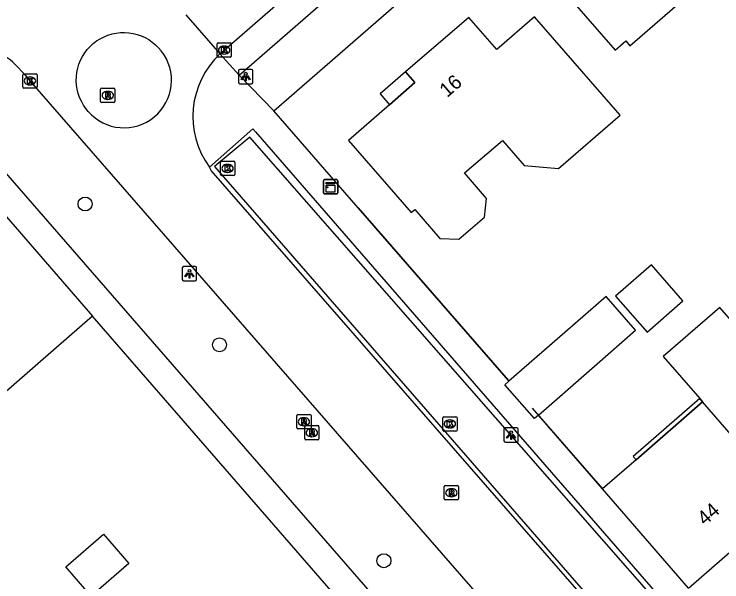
# Model space of a CAD drawing. Extents: x 155888 to 156864, y 383882 to 384671.
# Drawn here: x 156371.55 to 156421.04, y 384408.33 to 384448.02 of the extents above; entities that cross this region are included whole.
import ezdxf

# ---------------------------------------------------------------- set-up
doc = ezdxf.new("R2010")
doc.units = 0
for name, color, linetype in [('IMGEO_Boom', 7, 'Continuous'), ('IMGEO_Greppel_droge_sloot', 7, 'Continuous'), ('IMGEO_Kast', 7, 'Continuous'), ('IMGEO_Kolk', 7, 'Continuous'), ('IMGEO_Lichtpunt', 7, 'Continuous'), ('IMGEO_Muur', 7, 'Continuous'), ('IMGEO_Pand', 7, 'Continuous'), ('IMGEO_Pand_nummerreeks', 7, 'Continuous'), ('IMGEO_Pand_overbouw', 7, 'Continuous'), ('IMGEO_Rijbaan_lokaal_gesloten', 7, 'Continuous'), ('IMGEO_Rijbaan_lokaal_open', 7, 'Continuous'), ('IMGEO_Rioolput', 7, 'Continuous'), ('IMGEO_Voetpad_open', 7, 'Continuous')]:
    doc.layers.add(name, color=color, linetype=linetype)

msp = doc.modelspace()

# ---------------------------------------------------------------- linework, layer by layer
at = {"layer": 'IMGEO_Boom'}
for centre in [(156376.512, 384434.748), (156385.91, 384424.901), (156397.411, 384409.805)]:
    msp.add_circle(centre, 0.489, dxfattribs=at)
at = {"layer": 'IMGEO_Greppel_droge_sloot'}
msp.add_lwpolyline([(156417.878, 384400.227), (156418.055, 384400.375), (156420.409, 384402.472), (156388.034, 384439.426), (156385.569, 384437.381), (156417.878, 384400.227)], dxfattribs=at)
at = {"layer": 'IMGEO_Kast'}
for p, q in [((156393.178, 384435.529), (156393.178, 384436.37)), ((156393.178, 384436.37), (156393.178, 384435.529)), ((156393.253, 384436.454), (156394.094, 384436.454)), ((156394.094, 384436.454), (156393.253, 384436.454)), ((156394.178, 384436.379), (156394.178, 384435.538)), ((156394.178, 384435.538), (156394.178, 384436.379)), ((156394.103, 384435.454), (156393.262, 384435.454)), ((156393.262, 384435.454), (156394.103, 384435.454))]:
    msp.add_line(p, q, dxfattribs=at)
for points in [[(156393.373, 384436.244), (156393.973, 384436.244), (156393.973, 384436.159), (156393.373, 384436.159), (156393.373, 384436.244)], [(156393.373, 384436.069), (156393.973, 384436.069), (156393.973, 384435.58), (156393.373, 384435.58), (156393.373, 384436.069)]]:
    msp.add_lwpolyline(points, dxfattribs=at)
msp.add_circle((156393.457, 384435.918), 0.0377, dxfattribs=at)
for centre, start, end in [((156393.256, 384436.376), 92.4484, 184.2845), ((156393.256, 384436.376), 92.4484, 184.2845), ((156394.1, 384436.376), 2.4484, 94.2845), ((156394.1, 384436.376), 2.4484, 94.2845), ((156393.256, 384435.532), 182.4484, 274.2845), ((156393.256, 384435.532), 182.4484, 274.2845), ((156394.1, 384435.532), 272.4484, 4.2845), ((156394.1, 384435.532), 272.4484, 4.2845)]:
    msp.add_arc(centre, 0.0779, start, end, dxfattribs=at)
at = {"layer": 'IMGEO_Kolk'}
for p, q in [((156385.738, 384445.086), (156385.738, 384445.938)), ((156385.813, 384446.012), (156386.665, 384446.012)), ((156386.226, 384445.792), (156386.251, 384445.792)), ((156386.739, 384445.938), (156386.739, 384445.086)), ((156386.249, 384445.232), (156386.224, 384445.232)), ((156386.665, 384445.012), (156385.813, 384445.012)), ((156372.157, 384442.931), (156372.157, 384443.783)), ((156372.232, 384443.857), (156373.084, 384443.857)), ((156372.645, 384443.637), (156372.67, 384443.637)), ((156373.158, 384443.783), (156373.158, 384442.931)), ((156372.668, 384443.077), (156372.643, 384443.077)), ((156373.084, 384442.857), (156372.232, 384442.857)), ((156385.976, 384436.809), (156385.976, 384437.661)), ((156386.051, 384437.735), (156386.903, 384437.735)), ((156386.977, 384437.661), (156386.977, 384436.809)), ((156386.464, 384437.515), (156386.489, 384437.515)), ((156386.903, 384436.735), (156386.051, 384436.735)), ((156386.487, 384436.955), (156386.462, 384436.955)), ((156401.598, 384419.87), (156402.45, 384419.87)), ((156401.523, 384418.944), (156401.523, 384419.796)), ((156402.011, 384419.65), (156402.036, 384419.65)), ((156402.524, 384419.796), (156402.524, 384418.944)), ((156402.45, 384418.87), (156401.598, 384418.87)), ((156402.034, 384419.09), (156402.009, 384419.09))]:
    msp.add_line(p, q, dxfattribs=at)
for points in [[(156385.738, 384445.086), (156385.738, 384445.938)], [(156385.813, 384446.012), (156386.665, 384446.012)], [(156386.059, 384445.712), (156386.182, 384445.712), (156386.182, 384445.561), (156386.312, 384445.712), (156386.476, 384445.712), (156386.33, 384445.561), (156386.483, 384445.312), (156386.331, 384445.312), (156386.246, 384445.476), (156386.182, 384445.409), (156386.182, 384445.312), (156386.059, 384445.312), (156386.059, 384445.712)], [(156386.739, 384445.938), (156386.739, 384445.086)], [(156386.665, 384445.012), (156385.813, 384445.012)], [(156372.157, 384442.931), (156372.157, 384443.783)], [(156372.232, 384443.857), (156373.084, 384443.857)], [(156373.158, 384443.783), (156373.158, 384442.931)], [(156372.478, 384443.557), (156372.601, 384443.557), (156372.601, 384443.406), (156372.731, 384443.557), (156372.895, 384443.557), (156372.749, 384443.406), (156372.902, 384443.157), (156372.75, 384443.157), (156372.665, 384443.321), (156372.601, 384443.254), (156372.601, 384443.157), (156372.478, 384443.157), (156372.478, 384443.557)], [(156373.084, 384442.857), (156372.232, 384442.857)], [(156385.976, 384436.809), (156385.976, 384437.661)], [(156386.051, 384437.735), (156386.903, 384437.735)], [(156386.977, 384437.661), (156386.977, 384436.809)], [(156386.297, 384437.435), (156386.42, 384437.435), (156386.42, 384437.284), (156386.55, 384437.435), (156386.714, 384437.435), (156386.568, 384437.284), (156386.721, 384437.035), (156386.569, 384437.035), (156386.484, 384437.199), (156386.42, 384437.132), (156386.42, 384437.035), (156386.297, 384437.035), (156386.297, 384437.435)], [(156386.903, 384436.735), (156386.051, 384436.735)], [(156401.598, 384419.87), (156402.45, 384419.87)], [(156401.523, 384418.944), (156401.523, 384419.796)], [(156401.844, 384419.57), (156401.967, 384419.57), (156401.967, 384419.419), (156402.097, 384419.57), (156402.261, 384419.57), (156402.115, 384419.419), (156402.268, 384419.17), (156402.116, 384419.17), (156402.031, 384419.334), (156401.967, 384419.267), (156401.967, 384419.17), (156401.844, 384419.17), (156401.844, 384419.57)], [(156402.524, 384419.796), (156402.524, 384418.944)], [(156402.45, 384418.87), (156401.598, 384418.87)]]:
    msp.add_lwpolyline(points, dxfattribs=at)
for centre, start, end in [((156385.815, 384445.936), 91.552, 178.448), ((156385.815, 384445.936), 91.552, 178.448), ((156386.663, 384445.936), 1.552, 88.448), ((156386.663, 384445.936), 1.552, 88.448), ((156385.815, 384445.088), 181.552, 268.448), ((156385.815, 384445.088), 181.552, 268.448), ((156386.663, 384445.088), 271.552, 358.448), ((156386.663, 384445.088), 271.552, 358.448), ((156372.234, 384443.781), 91.552, 178.448), ((156372.234, 384443.781), 91.552, 178.448), ((156373.082, 384443.781), 1.552, 88.448), ((156373.082, 384443.781), 1.552, 88.448), ((156372.234, 384442.933), 181.552, 268.448), ((156372.234, 384442.933), 181.552, 268.448), ((156373.082, 384442.933), 271.552, 358.448), ((156373.082, 384442.933), 271.552, 358.448), ((156386.053, 384437.659), 91.552, 178.448), ((156386.053, 384437.659), 91.552, 178.448), ((156386.901, 384437.659), 1.552, 88.448), ((156386.901, 384437.659), 1.552, 88.448), ((156386.053, 384436.811), 181.552, 268.448), ((156386.053, 384436.811), 181.552, 268.448), ((156386.901, 384436.811), 271.552, 358.448), ((156386.901, 384436.811), 271.552, 358.448), ((156401.6, 384419.794), 91.552, 178.448), ((156401.6, 384419.794), 91.552, 178.448), ((156402.448, 384419.794), 1.552, 88.448), ((156402.448, 384419.794), 1.552, 88.448), ((156401.6, 384418.946), 181.552, 268.448), ((156401.6, 384418.946), 181.552, 268.448), ((156402.448, 384418.946), 271.552, 358.448), ((156402.448, 384418.946), 271.552, 358.448)]:
    msp.add_arc(centre, 0.0765, start, end, dxfattribs=at)
for centre, major_axis, ratio, start_param, end_param in [((156386.225, 384445.512), (-0.387, 0.002), 0.722429, 4.712389, 7.853982), ((156386.25, 384445.512), (-0.39, 0.002), 0.717154, 1.570796, 4.712389), ((156372.644, 384443.357), (-0.387, 0.002), 0.722429, 4.712389, 7.853982), ((156372.669, 384443.357), (-0.39, 0.002), 0.717154, 1.570796, 4.712389), ((156386.463, 384437.235), (-0.387, 0.002), 0.722429, 4.712389, 7.853982), ((156386.488, 384437.235), (-0.39, 0.002), 0.717154, 1.570796, 4.712389), ((156402.01, 384419.37), (-0.387, 0.002), 0.722429, 4.712389, 7.853982), ((156402.035, 384419.37), (-0.39, 0.002), 0.717154, 1.570796, 4.712389)]:
    msp.add_ellipse(centre, major_axis=major_axis, ratio=ratio, start_param=start_param, end_param=end_param, dxfattribs=at)
at = {"layer": 'IMGEO_Lichtpunt'}
for p, q in [((156387.248, 384444.063), (156387.248, 384443.256)), ((156387.248, 384444.063), (156387.248, 384443.256)), ((156388.15, 384444.158), (156387.342, 384444.158)), ((156388.15, 384444.158), (156387.342, 384444.158)), ((156388.244, 384443.256), (156388.244, 384444.063)), ((156388.244, 384443.256), (156388.244, 384444.063)), ((156387.342, 384443.162), (156388.15, 384443.162)), ((156387.342, 384443.162), (156388.15, 384443.162)), ((156383.311, 384430.277), (156383.311, 384429.47)), ((156383.311, 384430.277), (156383.311, 384429.47)), ((156384.213, 384430.372), (156383.405, 384430.372)), ((156384.213, 384430.372), (156383.405, 384430.372)), ((156384.307, 384429.47), (156384.307, 384430.277)), ((156384.307, 384429.47), (156384.307, 384430.277)), ((156383.405, 384429.376), (156384.213, 384429.376)), ((156383.405, 384429.376), (156384.213, 384429.376)), ((156405.808, 384418.991), (156405.808, 384418.184)), ((156405.808, 384418.991), (156405.808, 384418.184)), ((156406.71, 384419.086), (156405.902, 384419.086)), ((156406.71, 384419.086), (156405.902, 384419.086)), ((156406.804, 384418.184), (156406.804, 384418.991)), ((156406.804, 384418.184), (156406.804, 384418.991)), ((156405.902, 384418.09), (156406.71, 384418.09)), ((156405.902, 384418.09), (156406.71, 384418.09))]:
    msp.add_line(p, q, dxfattribs=at)
for points in [[(156387.622, 384443.727), (156387.661, 384443.699), (156387.473, 384443.437), (156387.435, 384443.464), (156387.622, 384443.727)], [(156387.724, 384443.679), (156387.771, 384443.679), (156387.771, 384443.357), (156387.724, 384443.357), (156387.724, 384443.679)], [(156387.834, 384443.699), (156387.872, 384443.726), (156388.059, 384443.464), (156388.02, 384443.436), (156387.834, 384443.699)], [(156383.685, 384429.941), (156383.724, 384429.913), (156383.536, 384429.651), (156383.498, 384429.678), (156383.685, 384429.941)], [(156383.787, 384429.893), (156383.834, 384429.893), (156383.834, 384429.571), (156383.787, 384429.571), (156383.787, 384429.893)], [(156383.897, 384429.913), (156383.935, 384429.94), (156384.122, 384429.678), (156384.083, 384429.65), (156383.897, 384429.913)], [(156406.182, 384418.655), (156406.221, 384418.627), (156406.033, 384418.365), (156405.995, 384418.392), (156406.182, 384418.655)], [(156406.284, 384418.607), (156406.331, 384418.607), (156406.331, 384418.285), (156406.284, 384418.285), (156406.284, 384418.607)], [(156406.394, 384418.627), (156406.432, 384418.654), (156406.619, 384418.392), (156406.58, 384418.364), (156406.394, 384418.627)]]:
    msp.add_lwpolyline(points, dxfattribs=at)
for centre in [(156387.747, 384443.861), (156383.81, 384430.075), (156406.307, 384418.789)]:
    msp.add_circle(centre, 0.0994, dxfattribs=at)
for centre, start, end in [((156387.342, 384444.063), 90, 180), ((156387.342, 384444.063), 90, 180), ((156388.15, 384444.063), 0, 90), ((156388.15, 384444.063), 0, 90), ((156387.342, 384443.256), 180, 270), ((156387.342, 384443.256), 180, 270), ((156388.15, 384443.256), 270, 0), ((156388.15, 384443.256), 270, 360), ((156383.405, 384430.277), 90, 180), ((156383.405, 384430.277), 90, 180), ((156384.213, 384430.277), 0, 90), ((156384.213, 384430.277), 0, 90), ((156383.405, 384429.47), 180, 270), ((156383.405, 384429.47), 180, 270), ((156384.213, 384429.47), 270, 0), ((156384.213, 384429.47), 270, 360), ((156405.902, 384418.991), 90, 180), ((156405.902, 384418.991), 90, 180), ((156406.71, 384418.991), 0, 90), ((156406.71, 384418.991), 0, 90), ((156405.902, 384418.184), 180, 270), ((156405.902, 384418.184), 180, 270), ((156406.71, 384418.184), 270, 0), ((156406.71, 384418.184), 270, 360)]:
    msp.add_arc(centre, 0.0946, start, end, dxfattribs=at)
at = {"layer": 'IMGEO_Muur'}
for points in [[(156395.616, 384434.473), (156406.119, 384422.397)], [(156404.4, 384395.417), (156377.02, 384426.898)], [(156407.789, 384420.472), (156412.691, 384414.822)]]:
    msp.add_lwpolyline(points, dxfattribs=at)
at = {"layer": 'IMGEO_Pand'}
for points in [[(156413.577, 384445.494), (156414.331, 384446.149), (156414.62, 384445.817), (156420.398, 384450.838), (156422.875, 384447.986), (156425.485, 384450.254), (156426.684, 384448.874), (156429.083, 384450.958), (156421.59, 384459.589), (156418.053, 384456.578), (156416.369, 384458.556), (156415.608, 384457.909), (156415.33, 384458.236), (156413.8, 384456.905), (156413.367, 384457.402), (156409.892, 384454.38), (156410.325, 384453.882), (156408.78, 384452.538), (156409.062, 384452.214), (156408.308, 384451.558), (156413.577, 384445.494)], [(156413.931, 384440.948), (156407.941, 384447.831), (156405.319, 384445.543), (156403.352, 384447.797), (156398.927, 384443.98), (156399.576, 384443.236), (156397.8, 384441.687), (156394.935, 384439.187), (156399.324, 384434.154), (156399.565, 384434.364), (156401.326, 384432.344), (156402.64, 384432.283), (156404.447, 384433.838), (156404.585, 384435.135), (156403.052, 384436.916), (156405.698, 384439.194), (156407.212, 384437.436), (156409.623, 384437.24), (156413.931, 384440.948)], [(156377.02, 384426.898), (156374.487, 384424.698), (156369.682, 384420.523), (156362.599, 384428.676), (156367.375, 384432.826), (156369.937, 384435.051)], [(156369.937, 384435.051), (156377.02, 384426.898)], [(156413.614, 384428.304), (156415.812, 384425.784), (156418.323, 384427.975), (156416.125, 384430.494), (156413.614, 384428.304)], [(156408.214, 384419.982), (156412.131, 384423.4), (156415.013, 384425.914), (156412.949, 384428.279), (156410.068, 384425.765), (156406.157, 384422.354)], [(156426.485, 384426.811), (156424.278, 384424.893), (156423.652, 384424.349), (156423.456, 384424.576), (156420.898, 384427.52), (156416.935, 384424.076), (156419.499, 384421.137), (156419.696, 384420.911)], [(156408.214, 384419.982), (156407.937, 384419.741), (156405.873, 384422.106), (156406.157, 384422.354)], [(156419.696, 384420.911), (156415.043, 384416.866), (156412.691, 384414.822)], [(156425.718, 384413.968), (156419.696, 384420.911)], [(156418.721, 384407.887), (156412.691, 384414.822)], [(156418.721, 384407.887), (156421.064, 384409.924), (156425.718, 384413.968)], [(156375.158, 384409.368), (156377.792, 384411.656), (156379.566, 384409.613), (156376.932, 384407.325), (156375.158, 384409.368)]]:
    msp.add_lwpolyline(points, dxfattribs=at)
at = {"layer": 'IMGEO_Pand_overbouw'}
for points in [[(156398.927, 384443.98), (156397.142, 384442.441), (156397.8, 384441.687), (156399.576, 384443.236)], [(156419.696, 384420.911), (156419.499, 384421.137), (156414.847, 384417.093), (156415.043, 384416.866)]]:
    msp.add_lwpolyline(points, close=True, dxfattribs=at)
at = {"layer": 'IMGEO_Rijbaan_lokaal_gesloten'}
for points in [[(156385.943, 384445.252), (156386.238, 384445.513), (156426.553, 384480.577), (156426.95, 384480.922), (156448.887, 384500), (156466.428, 384515.254), (156476.04, 384523.575), (156500, 384544.42), (156507.992, 384551.373), (156512.78, 384555.514), (156551.569, 384589.179), (156578.098, 384612.298), (156579.282, 384613.324)], [(156383.559, 384447.983), (156385.943, 384445.252)], [(156371.828, 384444.303), (156372.336, 384443.723), (156372.657, 384443.356), (156413.578, 384396.396), (156413.827, 384396.051)], [(156418.303, 384400.017), (156417.943, 384399.73), (156385.335, 384437.1), (156385.213, 384437.321)]]:
    msp.add_lwpolyline(points, dxfattribs=at)
for centre, radius, start, end in [((156368.367, 384441.125), 4.699, 42.5519, 140.96), ((156390.074, 384440.873), 6.02, 133.328, 216.1542)]:
    msp.add_arc(centre, radius, start, end, dxfattribs=at)
at = {"layer": 'IMGEO_Rijbaan_lokaal_open'}
msp.add_lwpolyline([(156376.726, 384441.227), (156376.565, 384441.424), (156376.397, 384441.669), (156376.252, 384441.928), (156376.13, 384442.198), (156376.033, 384442.479), (156375.961, 384442.767), (156375.916, 384443.06), (156375.896, 384443.356), (156375.904, 384443.653), (156375.938, 384443.948), (156375.998, 384444.239), (156376.083, 384444.523), (156376.194, 384444.798), (156376.329, 384445.062), (156376.487, 384445.314), (156376.667, 384445.55), (156376.867, 384445.769), (156377.086, 384445.969), (156377.322, 384446.149), (156377.573, 384446.307), (156377.837, 384446.443), (156378.113, 384446.554), (156378.397, 384446.64), (156378.687, 384446.7), (156378.982, 384446.734), (156379.279, 384446.741), (156379.575, 384446.722), (156379.868, 384446.677), (156380.156, 384446.606), (156380.437, 384446.509), (156380.708, 384446.387), (156380.967, 384446.242), (156381.211, 384446.074), (156381.44, 384445.885), (156381.651, 384445.677), (156381.843, 384445.45)], dxfattribs=at)
msp.add_arc((156379.237, 384443.396), 3.318, 220.8228, 38.2421, dxfattribs=at)
at = {"layer": 'IMGEO_Rioolput'}
for p, q in [((156377.599, 384441.92), (156377.599, 384442.772)), ((156377.674, 384442.846), (156378.526, 384442.846)), ((156378.087, 384442.626), (156378.112, 384442.626)), ((156378.6, 384442.772), (156378.6, 384441.92)), ((156378.526, 384441.846), (156377.674, 384441.846)), ((156378.11, 384442.066), (156378.085, 384442.066)), ((156391.313, 384419.096), (156391.313, 384419.948)), ((156391.388, 384420.022), (156392.24, 384420.022)), ((156392.314, 384419.948), (156392.314, 384419.096)), ((156391.801, 384419.802), (156391.826, 384419.802)), ((156392.24, 384419.022), (156391.388, 384419.022)), ((156391.824, 384419.242), (156391.799, 384419.242)), ((156391.869, 384418.324), (156391.869, 384419.176)), ((156391.944, 384419.25), (156392.796, 384419.25)), ((156392.357, 384419.03), (156392.382, 384419.03)), ((156392.87, 384419.176), (156392.87, 384418.324)), ((156392.38, 384418.47), (156392.355, 384418.47)), ((156392.796, 384418.25), (156391.944, 384418.25)), ((156401.627, 384414.13), (156401.627, 384414.982)), ((156401.702, 384415.056), (156402.554, 384415.056)), ((156402.628, 384414.982), (156402.628, 384414.13)), ((156402.115, 384414.836), (156402.14, 384414.836)), ((156402.554, 384414.056), (156401.702, 384414.056)), ((156402.138, 384414.276), (156402.113, 384414.276))]:
    msp.add_line(p, q, dxfattribs=at)
for points in [[(156377.599, 384441.92), (156377.599, 384442.772)], [(156377.674, 384442.846), (156378.526, 384442.846)], [(156378.6, 384442.772), (156378.6, 384441.92)], [(156378.188, 384442.544), (156377.936, 384442.546), (156377.936, 384442.146)], [(156377.936, 384442.146), (156378.06, 384442.146), (156378.06, 384442.308), (156378.071, 384442.308)], [(156378.114, 384442.465), (156378.06, 384442.465), (156378.06, 384442.384)], [(156378.06, 384442.384), (156378.112, 384442.384)], [(156378.118, 384442.279), (156378.189, 384442.146), (156378.329, 384442.146), (156378.264, 384442.272)], [(156378.526, 384441.846), (156377.674, 384441.846)], [(156391.313, 384419.096), (156391.313, 384419.948)], [(156391.388, 384420.022), (156392.24, 384420.022)], [(156392.314, 384419.948), (156392.314, 384419.096)], [(156391.902, 384419.72), (156391.65, 384419.722), (156391.65, 384419.322)], [(156391.65, 384419.322), (156391.774, 384419.322), (156391.774, 384419.484), (156391.785, 384419.484)], [(156391.828, 384419.641), (156391.774, 384419.641), (156391.774, 384419.56)], [(156391.774, 384419.56), (156391.826, 384419.56)], [(156391.832, 384419.455), (156391.903, 384419.322), (156392.043, 384419.322), (156391.978, 384419.448)], [(156392.24, 384419.022), (156391.388, 384419.022)], [(156391.869, 384418.324), (156391.869, 384419.176)], [(156391.944, 384419.25), (156392.796, 384419.25)], [(156392.458, 384418.948), (156392.206, 384418.95), (156392.206, 384418.55)], [(156392.384, 384418.869), (156392.33, 384418.869), (156392.33, 384418.788)], [(156392.87, 384419.176), (156392.87, 384418.324)], [(156392.206, 384418.55), (156392.33, 384418.55), (156392.33, 384418.712), (156392.341, 384418.712)], [(156392.33, 384418.788), (156392.382, 384418.788)], [(156392.388, 384418.683), (156392.459, 384418.55), (156392.599, 384418.55), (156392.534, 384418.676)], [(156392.796, 384418.25), (156391.944, 384418.25)], [(156401.627, 384414.13), (156401.627, 384414.982)], [(156401.702, 384415.056), (156402.554, 384415.056)], [(156402.628, 384414.982), (156402.628, 384414.13)], [(156402.216, 384414.754), (156401.964, 384414.756), (156401.964, 384414.356)], [(156401.964, 384414.356), (156402.088, 384414.356), (156402.088, 384414.518), (156402.099, 384414.518)], [(156402.142, 384414.675), (156402.088, 384414.675), (156402.088, 384414.594)], [(156402.088, 384414.594), (156402.14, 384414.594)], [(156402.146, 384414.489), (156402.217, 384414.356), (156402.357, 384414.356), (156402.292, 384414.482)], [(156402.554, 384414.056), (156401.702, 384414.056)]]:
    msp.add_lwpolyline(points, dxfattribs=at)
for centre, radius, start, end in [((156377.676, 384442.77), 0.0765, 91.552, 178.448), ((156377.676, 384442.77), 0.0765, 91.552, 178.448), ((156378.524, 384442.77), 0.0765, 1.552, 88.448), ((156378.524, 384442.77), 0.0765, 1.552, 88.448), ((156378.07, 384442.255), 0.0533, 26.0293, 88.6989), ((156378.096, 384442.573), 0.19, 274.7715, 282.9687), ((156378.12, 384442.369), 0.0964, 77.0061, 93.1865), ((156378.134, 384442.426), 0.0378, 276.6634, 79.6772), ((156378.187, 384442.434), 0.109, 350.3612, 89.416), ((156378.185, 384442.434), 0.112, 277.5842, 350.9817), ((156378.169, 384442.219), 0.108, 29.5134, 73.7905), ((156377.676, 384441.922), 0.0765, 181.552, 268.448), ((156377.676, 384441.922), 0.0765, 181.552, 268.448), ((156378.524, 384441.922), 0.0765, 271.552, 358.448), ((156378.524, 384441.922), 0.0765, 271.552, 358.448), ((156391.39, 384419.946), 0.0765, 91.552, 178.448), ((156391.39, 384419.946), 0.0765, 91.552, 178.448), ((156392.238, 384419.946), 0.0765, 1.552, 88.448), ((156392.238, 384419.946), 0.0765, 1.552, 88.448), ((156391.784, 384419.431), 0.0533, 26.0293, 88.6989), ((156391.81, 384419.749), 0.19, 274.7715, 282.9687), ((156391.834, 384419.545), 0.0964, 77.0061, 93.1865), ((156391.848, 384419.602), 0.0378, 276.6634, 79.6772), ((156391.901, 384419.61), 0.109, 350.3612, 89.416), ((156391.899, 384419.61), 0.112, 277.5842, 350.9817), ((156391.883, 384419.395), 0.108, 29.5134, 73.7905), ((156391.39, 384419.098), 0.0765, 181.552, 268.448), ((156391.39, 384419.098), 0.0765, 181.552, 268.448), ((156391.946, 384419.174), 0.0765, 91.552, 178.448), ((156391.946, 384419.174), 0.0765, 91.552, 178.448), ((156392.238, 384419.098), 0.0765, 271.552, 358.448), ((156392.238, 384419.098), 0.0765, 271.552, 358.448), ((156392.39, 384418.773), 0.0964, 77.0061, 93.1865), ((156392.404, 384418.83), 0.0378, 276.6634, 79.6772), ((156392.457, 384418.838), 0.109, 350.3612, 89.416), ((156392.455, 384418.838), 0.112, 277.5842, 350.9817), ((156392.794, 384419.174), 0.0765, 1.552, 88.448), ((156392.794, 384419.174), 0.0765, 1.552, 88.448), ((156391.946, 384418.326), 0.0765, 181.552, 268.448), ((156391.946, 384418.326), 0.0765, 181.552, 268.448), ((156392.34, 384418.659), 0.0533, 26.0293, 88.6989), ((156392.366, 384418.977), 0.19, 274.7715, 282.9687), ((156392.439, 384418.623), 0.108, 29.5134, 73.7905), ((156392.794, 384418.326), 0.0765, 271.552, 358.448), ((156392.794, 384418.326), 0.0765, 271.552, 358.448), ((156401.704, 384414.98), 0.0765, 91.552, 178.448), ((156401.704, 384414.98), 0.0765, 91.552, 178.448), ((156402.552, 384414.98), 0.0765, 1.552, 88.448), ((156402.552, 384414.98), 0.0765, 1.552, 88.448), ((156402.098, 384414.465), 0.0533, 26.0293, 88.6989), ((156402.124, 384414.783), 0.19, 274.7715, 282.9687), ((156402.148, 384414.579), 0.0964, 77.0061, 93.1865), ((156402.162, 384414.636), 0.0378, 276.6634, 79.6772), ((156402.215, 384414.644), 0.109, 350.3612, 89.416), ((156402.213, 384414.644), 0.112, 277.5842, 350.9817), ((156402.197, 384414.429), 0.108, 29.5134, 73.7905), ((156401.704, 384414.132), 0.0765, 181.552, 268.448), ((156401.704, 384414.132), 0.0765, 181.552, 268.448), ((156402.552, 384414.132), 0.0765, 271.552, 358.448), ((156402.552, 384414.132), 0.0765, 271.552, 358.448)]:
    msp.add_arc(centre, radius, start, end, dxfattribs=at)
for centre, major_axis, ratio, start_param, end_param in [((156378.086, 384442.346), (-0.387, 0.002), 0.722429, 4.712389, 7.853982), ((156378.111, 384442.346), (-0.39, 0.002), 0.717154, 1.570796, 4.712389), ((156391.8, 384419.522), (-0.387, 0.002), 0.722429, 4.712389, 7.853982), ((156391.825, 384419.522), (-0.39, 0.002), 0.717154, 1.570796, 4.712389), ((156392.356, 384418.75), (-0.387, 0.002), 0.722429, 4.712389, 7.853982), ((156392.381, 384418.75), (-0.39, 0.002), 0.717154, 1.570796, 4.712389), ((156402.114, 384414.556), (-0.387, 0.002), 0.722429, 4.712389, 7.853982), ((156402.139, 384414.556), (-0.39, 0.002), 0.717154, 1.570796, 4.712389)]:
    msp.add_ellipse(centre, major_axis=major_axis, ratio=ratio, start_param=start_param, end_param=end_param, dxfattribs=at)
at = {"layer": 'IMGEO_Voetpad_open'}
for points in [[(156387.279, 384443.752), (156428.273, 384479.396), (156451.969, 384500), (156477.412, 384522.142), (156500, 384541.752), (156509.198, 384549.738), (156578.017, 384609.497), (156582.526, 384613.433)], [(156389.717, 384441.255), (156430.543, 384476.776), (156432.323, 384478.325), (156457.305, 384500), (156479.838, 384519.516), (156485.227, 384524.21)], [(156385.943, 384445.252), (156387.279, 384443.752)], [(156409.66, 384392.433), (156367.685, 384440.674), (156364.717, 384444.085)], [(156387.279, 384443.752), (156389.717, 384441.255)], [(156406.157, 384422.354), (156406.119, 384422.397), (156395.616, 384434.473), (156389.717, 384441.255)], [(156385.213, 384437.321), (156388.252, 384439.996), (156388.424, 384439.798), (156421.023, 384402.28)], [(156408.123, 384391.086), (156404.4, 384395.417), (156377.02, 384426.898)], [(156412.691, 384414.822), (156408.214, 384419.982)]]:
    msp.add_lwpolyline(points, dxfattribs=at)

# ---------------------------------------------------------------- texts
at = {"layer": 'IMGEO_Pand_nummerreeks'}
for s, rotation, p in [('16', 40.7774, (156401.833, 384442.154)), ('44', 40.9961, (156419.859, 384412.217))]:
    msp.add_text(s, height=1, rotation=rotation, dxfattribs=at).set_placement(p)

doc.saveas('drawing.dxf')
